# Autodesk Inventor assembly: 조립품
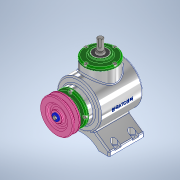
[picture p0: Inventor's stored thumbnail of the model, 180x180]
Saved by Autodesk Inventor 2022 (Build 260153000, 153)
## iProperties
Created: 2023-04
Part Number: 조립품
Document SubType Name: Assembly
Designer: Admin
Author: Admin
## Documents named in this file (17)
- C:\Users\Admin\Desktop\730411V1006\조립품.iam
- C:\Users\Admin\Desktop\730411V1006\본체.ipt
- C:\Users\Admin\Desktop\730411V1006\커버.ipt
- C:\Users\Admin\Desktop\730411V1006\베어링 6203.ipt
- C:\Users\Admin\Desktop\730411V1006\오일실 17 x 32 x 8.ipt
- C:\Users\Admin\Desktop\730411V1006\메인 축.ipt
- 메인 축.ipt
- C:\Users\Admin\Desktop\730411V1006\Ű 5 x 5 x 14.ipt
- C:\Users\Admin\Desktop\730411V1006\메인 베벨기어.ipt
- C:\Users\Admin\Desktop\730411V1006\서브 축.ipt
- 서브 축.ipt
- C:\Users\Admin\Desktop\730411V1006\Ű 4 x 4 x 14.ipt
- C:\Users\Admin\Desktop\730411V1006\서브 베벨기어.ipt
- C:\Users\Admin\Desktop\730411V1006\V-벨트풀리.ipt
- C:\Users\Admin\Desktop\730411V1006\볼트 M4 x 10.ipt
- C:\Users\Admin\Desktop\730411V1006\와셔 4 x 16.ipt
- C:\Users\Admin\Desktop\730411V1006\육각볼트 M4 x 8.ipt
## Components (4 placed, 3 different names)
1. Ű 5 x 5 x 14:1
2. Ű 4 x 4 x 14:1
3. V-벨트풀리:1
4. Ű 4 x 4 x 14:2
